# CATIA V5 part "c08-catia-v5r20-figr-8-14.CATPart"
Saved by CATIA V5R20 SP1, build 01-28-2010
Part number: Part1
Bounding box of the stored display mesh (mm): x 50 to 200, y -149.804 to 70, z -150 to 40
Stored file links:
  D:\v5_r20\psrt_files_downloaded\c08-catia-v5r20-prt\c08-catia-v5r20-figr-8-14.CATPart
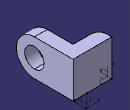
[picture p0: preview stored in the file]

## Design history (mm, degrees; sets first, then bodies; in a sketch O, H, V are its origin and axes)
AxisSystem1: origin (150, 70, -150), X (-1, 0, 0), Y (0, -1, 0), Z (0, 0, 1)
AxisSystem2: origin (50, 70, -100), X (1, 0, 0), Y (0, 0, 1), Z (0, -1, 0)
Body1 (main body)
  Sketch1 on yz-plane, origin (0, 0, 0), H (0, 1, 0), V (0, 0, 1)
    arc A1 centre (0, 0) radius 70 from (70, 0) to (-70, 0) ccw
    point P1 (70, 0)
    point P2 (-70, 0)
    line L1 (-70, 0) -> (-70, -150)
    line L2 (-70, -150) -> (70, -150)
    line L3 (70, -150) -> (70, 0)
    circle A2 centre (0, 0) radius 37.5
    radius A1 = 70
    radius A2 = 37.5
    distance O L2 = 150
    coincidence: P1 H, P2 H
    tangency: L1 A1, L3 A1
    horizontal: L2 H
  Pad1: profile Sketch1, direction (1, 0, 0), length 50
  Sketch2 on face of Pad1, origin (50, 0, 0), H (0, 1, 0), V (0, 0, 1)
    line L1 (-70, -150) -> (70, -150)
    line L2 (70, -150) -> (70, -100)
    line L3 (70, -100) -> (-70, -100)
    line L4 (-70, -100) -> (-70, -150)
    reference projected line E1 (-70, -150) -> (70, -150) from edge [face of Pad1 | face of Pad1]
    reference projected line E2 (-70, 0) -> (-70, -150) from edge [face of Pad1 | face of Pad1]
    reference projected line E3 (70, -150) -> (70, 0) from edge [face of Pad1 | face of Pad1]
    length L2 = 50
    horizontal: L1 H, L3 H
    vertical: L2 V, L4 V
    coincidence: L1 E1, E2 L4, L2 E3
  Pad2: profile Sketch2, direction (1, 0, 0), length 100
  Fillet1: radius 30, on edge [face of Pad2 | face of Pad2]
  AxisToAxis1: ToTransfor Fillet1, AxisOrigin AxisSystem1, Axis AxisSystem2
  Sketch3 on face of Pad1, origin (50, 0, 0), H (0, 1, 0), V (0, 0, 1)
    point P1 (45.5554, 53.148)
    reference projected arc E1 centre (0, 0) radius 70 from (70, 0) to (-70, 0) ccw from edge [face of Pad1 | face of Pad1]
    coincidence: P1 E1
  Sketch4 on face of Pad2, origin (0, 0, -100), H (1, 0, 0), V (0, 1, 0)
    point P1 (110, 20)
